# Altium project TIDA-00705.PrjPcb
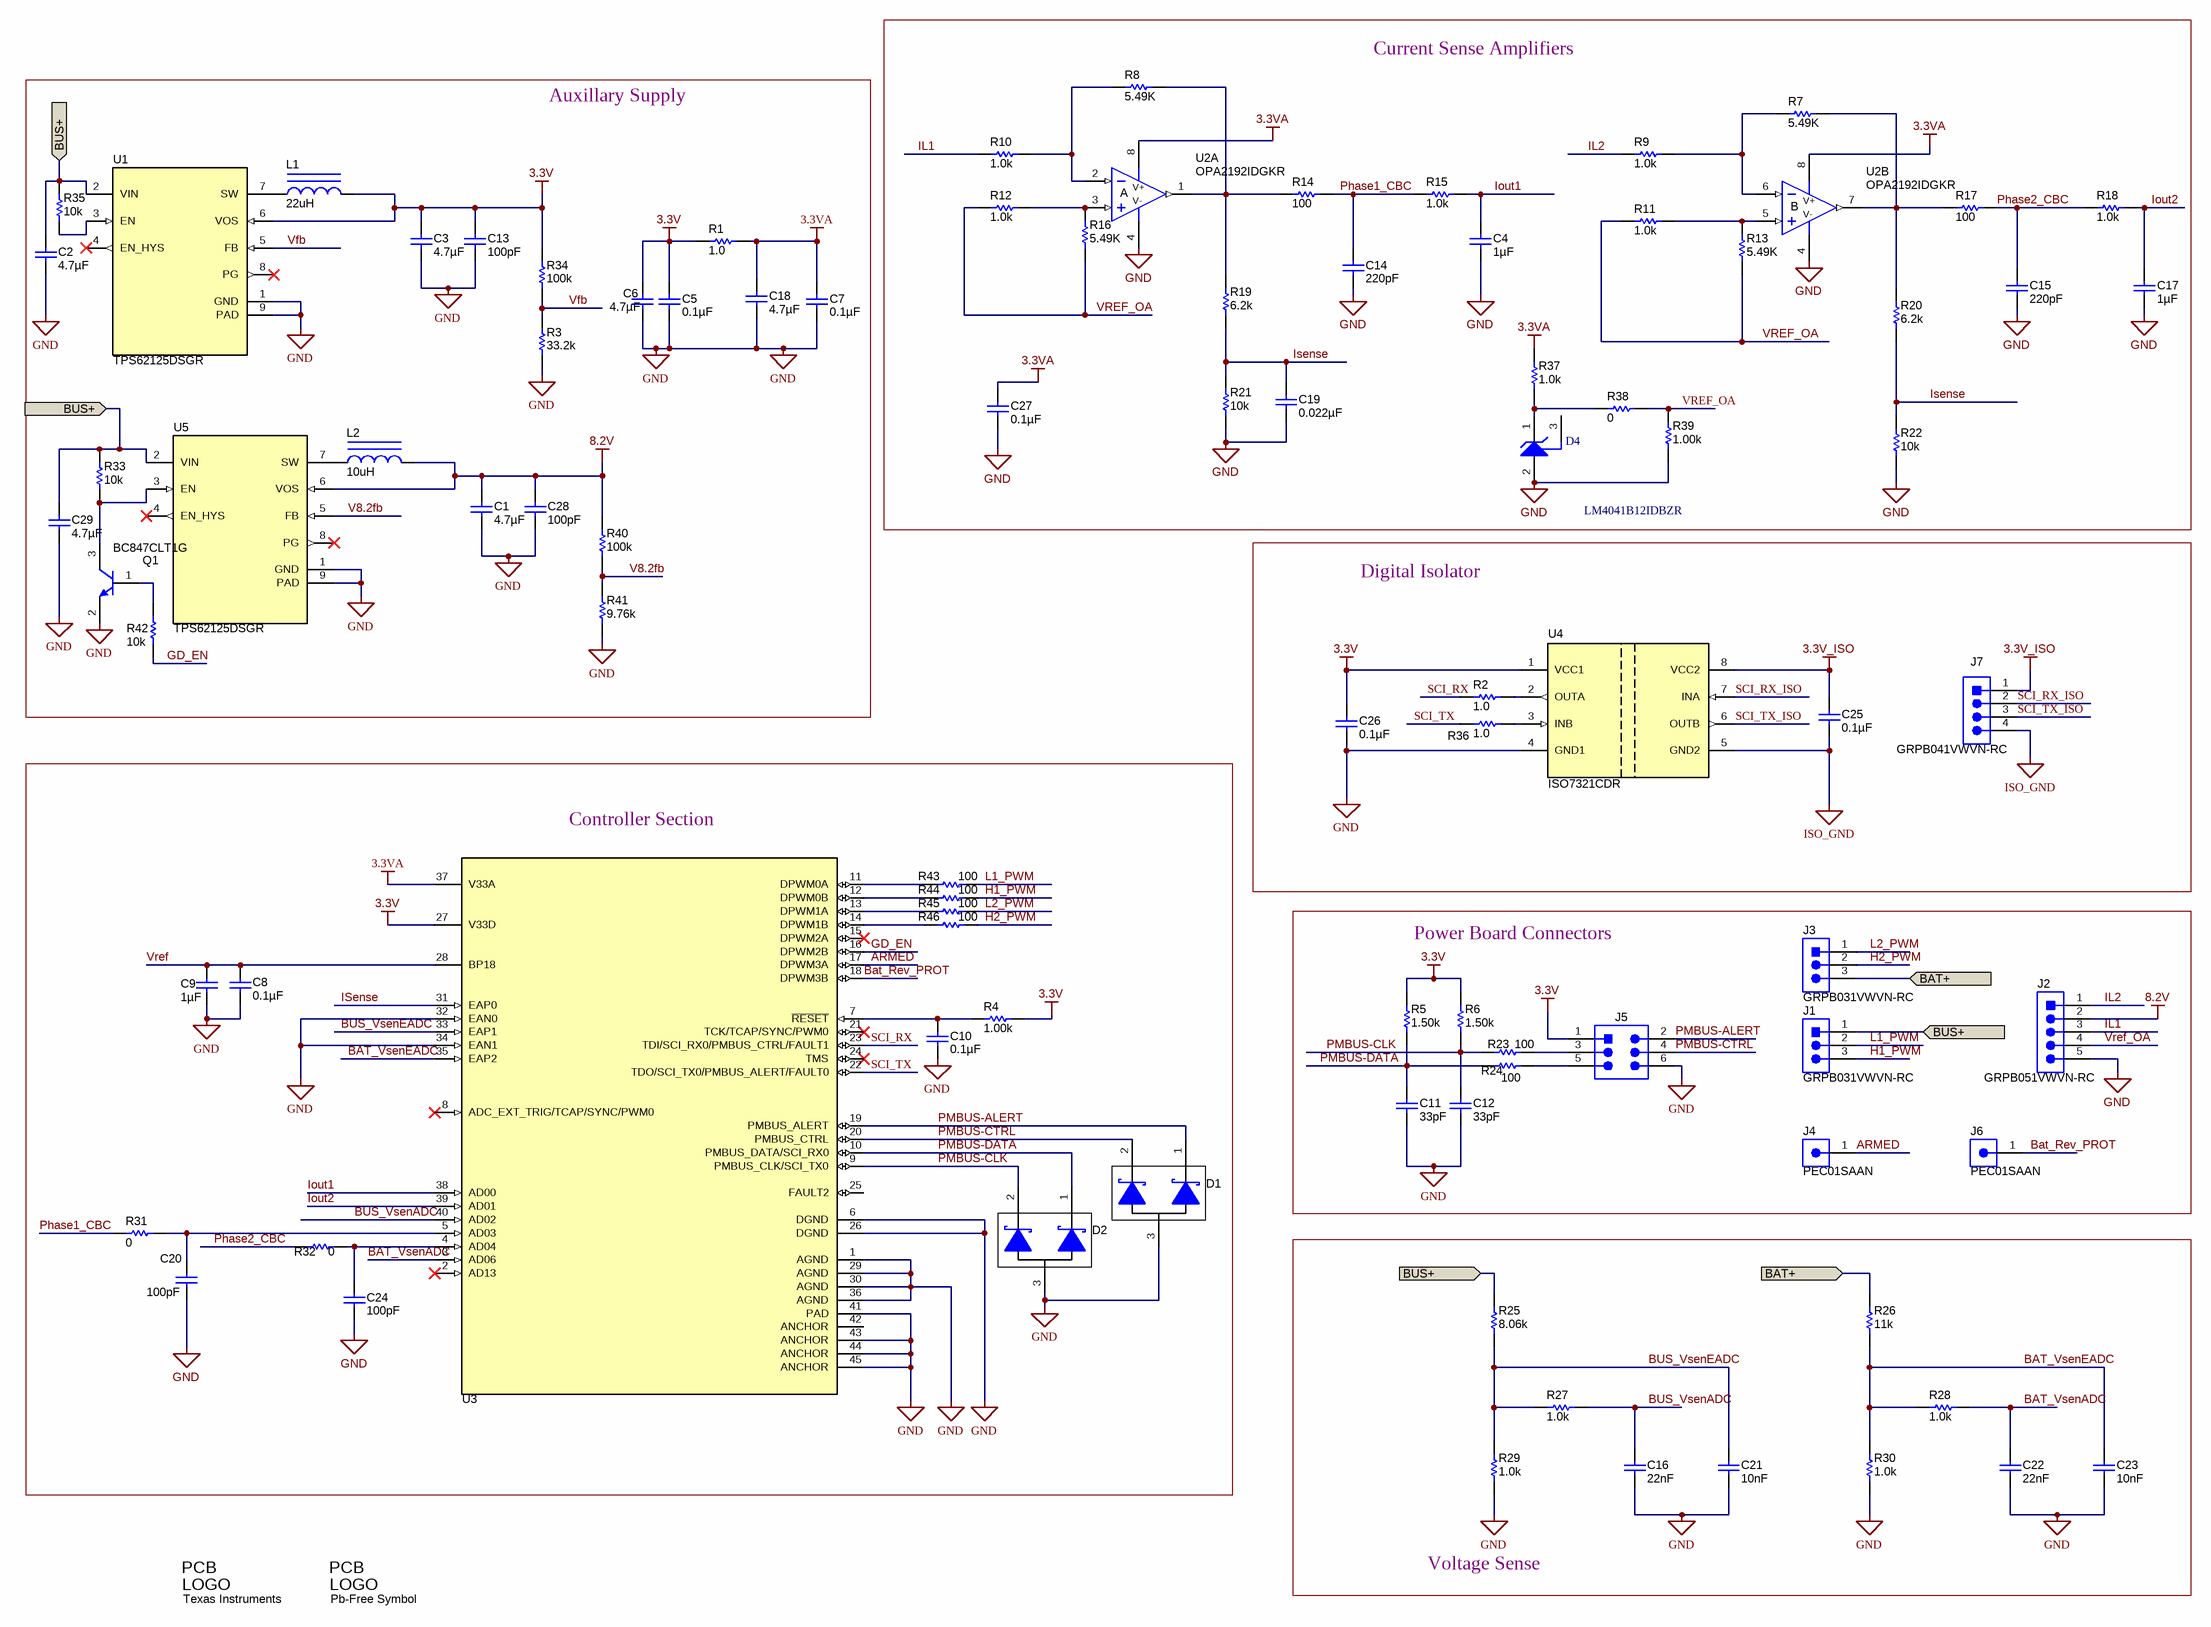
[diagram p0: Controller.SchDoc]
CopyrightYear: 2016; EVM_Orderable: N/A; PCB_Layout: Rajasekar; PCB_Rev: RevA; PRJ_Customer: Public Release; PRJ_Engineer: RAM; PRJ_Number: TIDA-00705; PRJ_Title: 720W Bidirectional Power Supply for LES; SCH_Rev: RevA; TechSupport: http://www.ti.com/support; TID: TIDA-00705
1 sheet, 95 parts. Net scope: flat (ports and power ports of the same name join across sheets).
Board file: TIDA-00705_Controller_20160414.PcbDoc

## Sheet Controller.SchDoc
size 431 x 355 mm; Date: Not shown in title block; ApprovedBy: Not shown in title block; CheckedBy: Not shown in title block; Author: Not shown in title block; CompanyName: Not shown in title block; Engineer: Not shown in title block; Organization: Not shown in title block; Address1: Not shown in title block; Address2: Not shown in title block; Address3: Not shown in title block; Address4: Not shown in title block; DocumentNumber: 1; Revision: Rev-A; SheetNumber: 1; SheetTotal: 1; PageSetup: Record=PageOptions¦CenterHorizontal=True¦CenterVertical=True¦PrintScale=1.00¦XCorrection=1.00¦YCorrection=1.00¦PrintKind=0¦BorderSize=5000000¦LeftOffset=0¦BottomOffset=0¦Orientation=2¦PaperLength=1000¦PaperWidth=1000¦Scale=100¦PaperSource=15¦PrintQuality=600¦MediaType=1¦DitherType=10¦PaperKind=Letter¦PrintScaleMode=1

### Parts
C1  ValueDisplayed: 4.7µF  [0603]  (hidden comment: CC0603KRX5R7BB475)
C2  ValueDisplayed: 4.7µF  [0603]  (hidden comment: CC0603KRX5R7BB475)
C3  ValueDisplayed: 4.7µF  [0603]  (hidden comment: CC0603KRX5R7BB475)
C4  ValueDisplayed: 1µF  [0402]  (hidden comment: C1005JB1V105K050BC)
C5  ValueDisplayed: 0.1µF  [0603]  (hidden comment: C0603C104K4RACTU)
C6  ValueDisplayed: 4.7µF  [0603]  (hidden comment: CC0603KRX5R7BB475)
C7  ValueDisplayed: 0.1µF  [0603]  (hidden comment: C0603C104K4RACTU)
C8  ValueDisplayed: 0.1µF  [0603]  (hidden comment: C0603C104K4RACTU)
C9  ValueDisplayed: 1µF  [0603]  (hidden comment: C0603C105K4PACTU)
C10  ValueDisplayed: 0.1µF  [0603]  (hidden comment: C0603C104K4RACTU)
C11  ValueDisplayed: 33pF  [0402]  (hidden comment: 885012005043)
C12  ValueDisplayed: 33pF  [0402]  (hidden comment: 885012005043)
C13  ValueDisplayed: 100pF  [0402]  (hidden comment: GRM1535C1H101JDD5D)
C14  ValueDisplayed: 220pF  [0402]  (hidden comment: C1005X7R1H221K)
C15  ValueDisplayed: 220pF  [0402]  (hidden comment: C1005X7R1H221K)
C16  ValueDisplayed: 22nF  [0402]  (hidden comment: GRM1535C1H101JDD5D)
C17  ValueDisplayed: 1µF  [0402]  (hidden comment: C1005JB1V105K050BC)
C18  ValueDisplayed: 4.7µF  [0603]  (hidden comment: CC0603KRX5R7BB475)
C19  ValueDisplayed: 0.022µF  [0402]  (hidden comment: C1005X7R1E223K)
C20  ValueDisplayed: 100pF  [0402]  (hidden comment: GRM1535C1H101JDD5D)
C21  ValueDisplayed: 10nF  [0402]  (hidden comment: GRM1535C1H101JDD5D)
C22  ValueDisplayed: 22nF  [0402]  (hidden comment: GRM1535C1H101JDD5D)
C23  ValueDisplayed: 10nF  [0402]  (hidden comment: GRM1535C1H101JDD5D)
C24  ValueDisplayed: 100pF  [0402]  (hidden comment: GRM1535C1H101JDD5D)
C25  ValueDisplayed: 0.1µF  [0603]  (hidden comment: 08053C104KAT2A)
C26  ValueDisplayed: 0.1µF  [0603]  (hidden comment: 08053C104KAT2A)
C27  ValueDisplayed: 0.1µF  [0402]  (hidden comment: C1005X7R1H104M)
C28  ValueDisplayed: 100pF  [0402]  (hidden comment: GRM1535C1H101JDD5D)
C29  ValueDisplayed: 4.7µF  [0603]  (hidden comment: CC0603KRX5R7BB475)
D1  SDM20N40A-7-F  [SOT-23]  (value not drawn)
D2  SDM20N40A-7-F  [SOT-23]  (value not drawn)
D4  LM4041B12IDBZR  [DBZ0003A_N]
J1  GRPB031VWVN-RC  [Sullins_GRPB031VWVN-RC]
J2  GRPB051VWVN-RC  [Sullins_GRPB051VWVN-RC]
J3  GRPB031VWVN-RC  [Sullins_GRPB031VWVN-RC]
J4  PEC01SAAN  [Sullins_PEC01SAAN]
J5  GRPB032VWVN-RC  [Sullins_GRPB032VWVN-RC]  (value not drawn)
J6  PEC01SAAN  [Sullins_PEC01SAAN]
J7  GRPB041VWVN-RC  [Sullins_GRPB041VWVN-RC]
L1  22uH  [WE_LQS_252012]
L2  10uH  [WE_LQS_252012]
Logo1  Texas Instruments  [TI_Symbol_Overlay_Small]  (no BOM)
Logo2  Pb-Free Symbol  [Pb-Free_Overlay_Small]  (no BOM)
Q1  BC847CLT1G  [SOT-23]
R1  ValueDisplayed: 1.0  [0402]  (hidden comment: CRCW04021R00JNED)
R2  ValueDisplayed: 1.0  [0402]  (hidden comment: CRCW04021R00JNED)
R3  ValueDisplayed: 33.2k  [0402]  (hidden comment: CRCW040233K2FKED)
R4  ValueDisplayed: 1.00k  [0402]  (hidden comment: ERJ-2RKF1001X)
R5  ValueDisplayed: 1.50k  [0402]  (hidden comment: CRCW04021K50FKED)
R6  ValueDisplayed: 1.50k  [0402]  (hidden comment: CRCW04021K50FKED)
R7  ValueDisplayed: 5.49K  [0402]  (hidden comment: ERA-2AEB5491X)
R8  ValueDisplayed: 5.49K  [0402]  (hidden comment: ERA-2AEB5491X)
R9  ValueDisplayed: 1.0k  [0402]  (hidden comment: RT0402BRD071KL)
R10  ValueDisplayed: 1.0k  [0402]  (hidden comment: RT0402BRD071KL)
R11  ValueDisplayed: 1.0k  [0402]  (hidden comment: RT0402BRD071KL)
R12  ValueDisplayed: 1.0k  [0402]  (hidden comment: RT0402BRD071KL)
R13  ValueDisplayed: 5.49K  [0402]  (hidden comment: ERA-2AEB5491X)
R14  ValueDisplayed: 100  [0402]  (hidden comment: RC0402FR-07100RL)
R15  ValueDisplayed: 1.0k  [0402]  (hidden comment: RT0402BRD071KL)
R16  ValueDisplayed: 5.49K  [0402]  (hidden comment: ERA-2AEB5491X)
R17  ValueDisplayed: 100  [0402]  (hidden comment: RC0402FR-07100RL)
R18  ValueDisplayed: 1.0k  [0402]  (hidden comment: RT0402BRD071KL)
R19  ValueDisplayed: 6.2k  [0402]  (hidden comment: RG1005P-622-B-T5)
R20  ValueDisplayed: 6.2k  [0402]  (hidden comment: RG1005P-622-B-T5)
R21  ValueDisplayed: 10k  [0402]  (hidden comment: ERA-2AEB103X)
R22  ValueDisplayed: 10k  [0402]  (hidden comment: ERA-2AEB103X)
R23  ValueDisplayed: 100  [0402]  (hidden comment: CRCW0402100RFKED)
R24  ValueDisplayed: 100  [0402]  (hidden comment: CRCW0402100RFKED)
R25  ValueDisplayed: 8.06k  [0402]  (hidden comment: CRCW04021K65FKED)
R26  ValueDisplayed: 11k  [0402]  (hidden comment: RG1005P-113-B-T5)
R27  ValueDisplayed: 1.0k  [0402]  (hidden comment: RT0402BRD071KL)
R28  ValueDisplayed: 1.0k  [0402]  (hidden comment: RT0402BRD071KL)
R29  ValueDisplayed: 1.0k  [0402]  (hidden comment: RT0402BRD071KL)
R30  ValueDisplayed: 1.0k  [0402]  (hidden comment: RT0402BRD071KL)
R31  ValueDisplayed: 0  [0402]  (hidden comment: CRCW04021K05FKED)
R32  ValueDisplayed: 0  [0402]  (hidden comment: CRCW04021K05FKED)
R33  ValueDisplayed: 10k  [0402]  (hidden comment: CRCW040210K0JNED)
R34  ValueDisplayed: 100k  [0402]  (hidden comment: CRCW0402100KFKED)
R35  ValueDisplayed: 10k  [0402]  (hidden comment: CRCW040210K0JNED)
R36  ValueDisplayed: 1.0  [0402]  (hidden comment: CRCW04021R00JNED)
R37  ValueDisplayed: 1.0k  [0402]  (hidden comment: RT0402BRD071KL)
R38  ValueDisplayed: 0  [0402]  (hidden comment: CRCW04020000Z0ED)
R39  ValueDisplayed: 1.00k  [0402]  (hidden comment: ERJ-2RKF1001X)
R40  ValueDisplayed: 100k  [0402]  (hidden comment: CRCW0402100KFKED)
R41  ValueDisplayed: 9.76k  [0402]  (hidden comment: CRCW04029K76FKED)
R42  ValueDisplayed: 10k  [0402]  (hidden comment: CRCW040210K0JNED)
R43  ValueDisplayed: 100  [0402]  (hidden comment: CRCW0402100RFKED)
R44  ValueDisplayed: 100  [0402]  (hidden comment: CRCW0402100RFKED)
R45  ValueDisplayed: 100  [0402]  (hidden comment: CRCW0402100RFKED)
R46  ValueDisplayed: 100  [0402]  (hidden comment: CRCW0402100RFKED)
U1  TPS62125DSGR  [DSG0008A]
U2  OPA2192IDGKR  [DGK0008A_N]  (parts A,B of 2)
U3  UCD3138RMHR  [RMH0040A]  (value not drawn)
U4  ISO7321CDR  [D0008B_N]
U5  TPS62125DSGR  [DSG0008A]

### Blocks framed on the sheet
Current Sense Amplifiers: C4 C14 C15 C17 C19 C27 D4 R7-R22 R37-R39 U2
Auxillary Supply: C1-C3 C5-C7 C13 C18 C28 C29 L1 L2 Q1 R1 R3 R33-R35 R40-R42 U1 U5
Digital Isolator: C25 C26 J7 R2 R36 U4
Controller Section: C8-C10 C20 C24 D1 D2 R4 R31 R32 R43-R46 U3
Power Board Connectors: C11 C12 J1-J6 R5 R6 R23 R24
Voltage Sense: C16 C21-C23 R25-R30

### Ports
BAT+ (in), BUS+ (in)

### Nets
3.3V: C3.2 C5.2 C6.2 C13.1 C26.1 J5.1 L1.2 R1.1 R4.2 R5.2 R6.2 R34.2 U1.6(VOS) U3.27(V33D) U4.1(VCC1)
3.3V_ISO: C25.1 J7.1 U4.8(VCC2)
3.3VA: C7.2 C18.2 C27.1 R1.2 R37.2 U2.8(V+) U3.37(V33A)
8.2V: C1.2 C28.1 J2.2 L2.2 R40.2 U5.6(VOS)
GND: C1.1 C2.1 C3.1 C4.2 C5.1 C6.1 C7.1 C8.1 C9.2 C10.2 C11.2 C12.2 C13.2 C14.2 C15.2 C16.2 C17.2 C18.1 C19.2 C20.2 C21.2 C22.2 C23.2 C24.2 C26.2 C27.2 C28.2 C29.1 D1.3(A) D2.3(A) D4.2(ANODE) J2.5 J5.6 Q1.2(E) R3.1 R21.1 R22.1 R29.1 R30.1 R39.1 R41.1 U1.1(GND) U1.9(PAD) U2.4(V-) U3.1(AGND) U3.6(DGND) U3.26(DGND) U3.29(AGND) U3.30(AGND) U3.32(EAN0) U3.34(EAN1) U3.36(AGND) U3.41(PAD) U3.43(ANCHOR) U3.44(ANCHOR) U3.45(ANCHOR) U4.4(GND1) U5.1(GND) U5.9(PAD)
ISO_GND: C25.2 J7.4 U4.5(GND2)
ARMED: J4.1 U3.17(DPWM3A)
BAT+: J3.3 R26.2 ; port BAT+
Bat_Rev_PROT: J6.1 U3.18(DPWM3B)
BAT_VsenADC: C22.1 R28.2 U3.3(AD06)
BAT_VsenEADC: C23.1 R26.1 R28.1 R30.2 U3.35(EAP2)
BUS+: C2.2 C29.2 J1.1 R25.2 R33.2 R35.2 U1.2(VIN) U5.2(VIN) ; port BUS+
BUS_VsenADC: C16.1 R27.2 U3.40(AD02)
BUS_VsenEADC: C21.1 R25.1 R27.1 R29.2 U3.33(EAP1)
GD_EN: R42.1 U3.16(DPWM2B)
H1_PWM: J1.3 R44.2
H2_PWM: J3.2 R46.2
IL1: J2.3 R10.1
IL2: J2.1 R9.1
Iout1: C4.1 R15.2 U3.38(AD00)
Iout2: C17.1 R18.2 U3.39(AD01)
Isense: C19.1 R19.1 R20.1 R21.2 R22.2 U3.31(EAP0)
L1_PWM: J1.2 R43.2
L2_PWM: J3.1 R45.2
Phase1_CBC: C14.1 R14.2 R15.1 R31.2
Phase2_CBC: C15.1 R17.2 R18.1 R32.2
PMBUS-ALERT: D1.1(A) J5.2 U3.19(PMBUS_ALERT)
PMBUS-CLK: C12.1 D2.2(K) R6.1 R23.1 U3.9(PMBUS_CLK/SCI_TX0)
PMBUS-CTRL: D1.2(K) J5.4 U3.20(PMBUS_CTRL)
PMBUS-DATA: C11.1 D2.1(A) R5.1 R24.1 U3.10(PMBUS_DATA/SCI_RX0)
SCI_RX: R2.1 U3.23(TDI/SCI_RX0/PMBUS_CTRL/FAULT1)
SCI_RX_ISO: J7.2 U4.7(INA)
SCI_TX: R36.1 U3.22(TDO/SCI_TX0/PMBUS_ALERT/FAULT0)
SCI_TX_ISO: J7.3 U4.6(OUTB)
V8.2fb: R40.1 R41.2 U5.5(FB)
Vfb: R3.2 R34.1 U1.5(FB)
Vref: C8.2 C9.1 U3.28(BP18)
VREF_OA: J2.4 R11.1 R12.1 R13.1 R16.1 R38.2 R39.2
NetC10_1: C10.1 R4.1 U3.7(~{RESET})
NetC20_1: C20.1 R31.1 U3.5(AD03)
NetC24_1: C24.1 R32.1 U3.4(AD04)
NetD4_1: D4.1(CATHODE) R37.1 R38.1
NetJ5_3: J5.3 R23.2
NetJ5_5: J5.5 R24.2
NetL1_1: L1.1 U1.7(SW)
NetL2_1: L2.1 U5.7(SW)
NetQ1_1: Q1.1(B) R42.2
NetQ1_3: Q1.3(C) R33.1 U5.3(EN)
NetR2_2: R2.2 U4.2(OUTA)
NetR7_1: R7.1 R17.1 R20.2 U2.7(OUT)
NetR7_2: R7.2 R9.2 U2.6(IN-)
NetR8_1: R8.1 R10.2 U2.2(IN-)
NetR8_2: R8.2 R14.1 R19.2 U2.1(OUT)
NetR11_2: R11.2 R13.2 U2.5(IN+)
NetR12_2: R12.2 R16.2 U2.3(IN+)
NetR35_1: R35.1 U1.3(EN)
NetR36_2: R36.2 U4.3(INB)
NetR43_1: R43.1 U3.11(DPWM0A)
NetR44_1: R44.1 U3.12(DPWM0B)
NetR45_1: R45.1 U3.13(DPWM1A)
NetR46_1: R46.1 U3.14(DPWM1B)

Not connected (* = marked no-connect by the designer): D4 3(NC); U1 4(EN_HYS)* 8(PG)*; U3 2(AD13)* 8(ADC_EXT_TRIG/TCAP/SYNC/PWM0)* 15(DPWM2A)* 21(TCK/TCAP/SYNC/PWM0)* 24(TMS)* 25(FAULT2) 42(ANCHOR); U5 4(EN_HYS)* 8(PG)*

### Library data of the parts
C1-C3 C6 C18 C29 = GRM188R61C475KAAJ: CAP, CERM, 4.7 µF, 16 V, +/- 10%, X5R, 0603; Manufacturer: Yageo; Value: 4.7uF; Polarized: N; CompType: Capacitor; U/M: EA; Cap_F: 0.0000047; Tolerance_%: 10; Value1: Unknown; VDC_V: 16; Value2: 16V; TaMin_C: -55; TaMax_C: 85
C4 C17 = C1005JB1V105K050BC: CAP, CERM, 1 µF, 35 V, +/- 10%, JB, 0402; Manufacturer: TDK; Polarized: N; CompType: Capacitor; Value: 1uF; U/M: EA; Cap_F: 0.000001; Tolerance_%: 10; Value1: Unknown; VDC_V: 35; Value2: 35V; TaMin_C: -25; TaMax_C: 85
C5 C7 C8 C10 = C0603C104K4RACTU: CAP, CERM, 0.1 µF, 16 V, +/- 10%, X7R, 0603; Manufacturer: Kemet; Value: 0.1uF; Polarized: N; CompType: Capacitor; U/M: EA; Cap_F: 0.0000001; Tolerance_%: 10; Value1: Unknown; VDC_V: 16; Value2: 16V; TaMin_C: -55; TaMax_C: 125
C9 = C0603C105K4PACTU: CAP, CERM, 1 µF, 16 V, +/- 10%, X5R, 0603; Manufacturer: Kemet; Polarized: N; CompType: Capacitor; Value: 1uF; U/M: EA; Cap_F: 0.000001; Tolerance_%: 10; Value1: Unknown; VDC_V: 16; Value2: 16V; TaMin_C: -55; TaMax_C: 85
C11 C12 = 885012005043: CAP, CERM, 33 pF, 25 V, +/- 5%, C0G/NP0, 0402; Manufacturer: Wurth Elektronik; Polarized: N; CompType: Capacitor; Value: 33pF; U/M: EA; Cap_F: 0.000000000033; Tolerance_%: 5; Value1: Unknown; VDC_V: 25; Value2: 25V; TaMin_C: -55; TaMax_C: 125
C13 C20-C24 C28 = GRM1535C1H101JDD5D: CAP, CERM, 100 pF, 50 V, +/- 5%, C0G/NP0, 0402; Manufacturer: MuRata; Polarized: N; CompType: Capacitor; Value: 100pF; U/M: EA; Cap_F: 0.0000000001; Tolerance_%: 5; Value1: Unknown; VDC_V: 50; Value2: 50V; TaMin_C: -55; TaMax_C: 125
C14 C15 = C1005X7R1H221K: CAP, CERM, 220 pF, 50 V, +/- 10%, X7R, 0402; Manufacturer: TDK; Polarized: N; CompType: Capacitor; Value: 220pF; U/M: EA; Cap_F: 0.00000000022; Tolerance_%: 10; ESR_ohm: 0.59; Value1: 0.59 ohm; VDC_V: 50; Value2: 50V; TaMin_C: -55; TaMax_C: 125
C16 = GRM1535C1H101JDD5D: CAP, CERM, 100 pF, 50 V, +/- 5%, C0G/NP0, 0402; Manufacturer: MuRata; Polarized: N; CompType: Capacitor; Value: 22nF; U/M: EA; Cap_F: 0.0000000001; Tolerance_%: 5; Value1: Unknown; VDC_V: 50; Value2: 50V; TaMin_C: -55; TaMax_C: 125
C19 = C1005X7R1E223K: CAP, CERM, 0.022 µF, 25 V, +/- 10%, X7R, 0402; Manufacturer: TDK; Polarized: N; CompType: Capacitor; Value: 0.022uF; U/M: EA; Cap_F: 0.000000022; Tolerance_%: 10; ESR_ohm: 0.0419; Value1: 0.0419 ohm; VDC_V: 25; Value2: 25V; TaMin_C: -55; TaMax_C: 125
C25 C26 = 08053C104KAT2A: CAP, CERM, 0.1 µF, 25 V, +/- 10%, X7R, 0805; Manufacturer: AVX; Polarized: N; CompType: Capacitor; Value: 0.1uF; U/M: EA; Cap_F: 0.0000001; Tolerance_%: 10; ESR_ohm: 0.28; Value1: 0.28 ohm; VDC_V: 25; Value2: 25V; TaMin_C: -55; TaMax_C: 125; Cap_Case: 0805
C27 = C1005X7R1H104M: CAP, CERM, 0.1 µF, 50 V, +/- 20%, X7R, 0402; Manufacturer: TDK; Polarized: N; CompType: Capacitor; Value: 0.1uF; U/M: EA; Cap_F: 0.0000001; Tolerance_%: 20; Value1: Unknown; VDC_V: 50; Value2: 50V; TaMin_C: -55; TaMax_C: 125
D1 D2 = SDM20N40A-7-F: Diode, Schottky, 40 V, 0.2 A, SOT-23; Manufacturer: Diodes Inc.; SymbolCreator: a0412235; U/M: EA; Vf_V: 0.45; Value: 40V; Value1: 0.2A; Value2: 0.45V; Io_A: 0.2; Vr_V: 40
D4 = LM4041B12IDBZR: Precision Micropower Shunt Voltage Reference, 0.2% accuracy, 1.2 V, 15 ppm / degC, 12 mA, -40 to 85 degC, 3-pin SOT-23 (DBZ), Green (RoHS & no Sb/Br); Manufacturer: Texas Instruments; Alternate PartNumber: Equivalent; Initial Accuracy @ 25/deg C(%): 0.2; Iout/Iz(Max)(mA): 12; Min Iz for Regulation(uA): 60; Rating: Catalog; Temp Coeff(Max)(ppm/ degree C): 100; Temp Coeff(Typ)(ppm/ degree C): 15; VO(V): 1.2
J1 J3 = GRPB031VWVN-RC: Header, 50mil, 3x1, Gold, TH; Manufacturer: Sullins Connector Solutions; SymbolCreator: a0799628; Gender: Male; Shrouded: N; Row_Count: 1
J2 = GRPB051VWVN-RC: Header, 50mil, 5x1, Gold, TH; Manufacturer: Sullins Connector Solutions; SymbolCreator: a0412235
J4 J6 = PEC01SAAN: Header, 1x1, Tin, TH; Manufacturer: Sullins Connector Solutions; SymbolCreator: a0412235; Pitch_mm: 2.54; Gender: Male; Shrouded: N; Row_Count: 1; Current_A: 3; Voltage_V: 1800; Cert_UL: Y
J5 = GRPB032VWVN-RC: Header, 50mil, 3x2, Gold, TH; Manufacturer: Sullins Connector Solutions; SymbolCreator: a0412235
J7 = GRPB041VWVN-RC: Header, 50mil, 4x1, Gold, TH; Manufacturer: Sullins Connector Solutions; SymbolCreator: a0412235
L1 = 74404024220: Inductor, Wirewound, Ferrite, 22 µH, 0.45 A, 0.91 ohm, SMD; Manufacturer: Wurth Elektronik; Ind_H: 22.0E-6; ValueDisplayed: 22µH; Imax_A: 0.45; Irms: 0.45A @ 40C rise; Isat: 0.55A @ 30% inductance drop; DCR_ohm: 0.91; Value2: 0.45A
L2 = 74404024100: Inductor, Wirewound, Ferrite, 10 µH, 0.47 A, 0.435 ohm, SMD; Manufacturer: Wurth Elektronik; Ind_H: 10.0E-6; ValueDisplayed: 10µH; Imax_A: 0.47; Irms: 0.47A @ 40C rise; Isat: 0.85A @ 30% inductance drop; DCR_ohm: 0.435; Value2: 0.47A
Logo1 = TI_Logo: Texas Instrument Corporate Signature; SymbolCreator: codlsc
Logo2 = Pb-Free: SymbolCreator: a0412235
Q1 = BC847CLT1G, ON Semiconductor: Transistor, NPN, 45 V, 0.1 A, SOT-23; CompType: BJT; PNP: 0; NPN: 1; Vceo_V: 45; Vcesat1_V: 0.7; Value: 45 V; IcRated_A: 0.1; Value1: 0.1 A; HfeMax: 800; TaMin_C: -55; TaMax_C: 150; U/M: EA
R1 R2 R36 = CRCW04021R00JNED: RES, 1.0, 5%, 0.063 W, 0402; Manufacturer: Vishay-Dale; CompType: Resistor; Value: 1.0; Res_ohm: 1; Value_Code: 1R00; Tolerance_%: 5; Power_W: 0.063; Value2: 0.063W; VDC_V: 50; TempCo: 200 ppm/C; EIA_Code: E24; U/M: EA
R3 = CRCW040233K2FKED: RES, 33.2 k, 1%, 0.063 W, 0402; Manufacturer: Vishay-Dale; CompType: Resistor; Value: 33.2k; Res_ohm: 33200; Value_Code: 33k2; Tolerance_%: 1; Power_W: 0.063; Value2: 0.063W; VDC_V: 50; TempCo: 100 ppm/C; EIA_Code: E96; U/M: EA
R4 R39 = ERJ-2RKF1001X: RES, 1.00 k, 1%, 0.1 W, 0402; Manufacturer: Panasonic; CompType: Resistor; Value: 1.00k; Res_ohm: 1000; Value_Code: 1k00; Tolerance_%: 1; Power_W: 0.1; Value2: 0.1W; VDC_V: 50; TempCo: 100 ppm/C; EIA_Code: E96; U/M: EA
R5 R6 = CRCW04021K50FKED: RES, 1.50 k, 1%, 0.063 W, 0402; Manufacturer: Vishay-Dale; CompType: Resistor; Value: 1.50k; Res_ohm: 1500; Value_Code: 1k50; Tolerance_%: 1; Power_W: 0.063; Value2: 0.063W; VDC_V: 50; TempCo: 100 ppm/C; EIA_Code: E96; U/M: EA
R7 R8 R13 R16 = CRCW04021K05FKED: RES, 5.49 k, 0.1%, 0.063 W, 0402; Manufacturer: Panasonic Electronic Corporation; CompType: Resistor; Value: 5.49K; Res_ohm: 5490; Tolerance_%: 1; Power_W: 0.063; Value2: 0.063W; VDC_V: 50; TempCo: 100 ppm/C; EIA_Code: E96; U/M: EA
R9-R11 R15 R27-R30 R37 = CRCW04021K05FKED: RES, 1.0 k, 0.1%, 0.063 W, 0402; Manufacturer: Vishay-Dale; CompType: Resistor; Value: 1.0k; Res_ohm: 1050; Value_Code: 1k; Tolerance_%: 1; Power_W: 0.063; Value2: 0.063W; VDC_V: 50; TempCo: 100 ppm/C; EIA_Code: E96; U/M: EA
R12 R18 = CRCW04021K05FKED: RES, 1.0 k, 0.1%, 0.063 W, 0402; Manufacturer: Vishay-Dale; CompType: Resistor; Value: 1.0k; Res_ohm: 1000; Value_Code: 1k; Tolerance_%: 1; Power_W: 0.063; Value2: 0.063W; VDC_V: 50; TempCo: 100 ppm/C; EIA_Code: E96; U/M: EA
R14 = CRCW04021K05FKED: RES, 100 1%, 0.063 W, 0402; Manufacturer: Vishay-Dale; CompType: Resistor; Value: 100; Res_ohm: 1050; Tolerance_%: 1; Power_W: 0.063; Value2: 0.063W; VDC_V: 50; TempCo: 100 ppm/C; EIA_Code: E96; U/M: EA
R17 = CRCW04021K05FKED: RES, 100, 1%, 0.063 W, 0402; Manufacturer: Vishay-Dale; CompType: Resistor; Value: 100; Tolerance_%: 1; Power_W: 0.063; Value2: 0.063W; VDC_V: 50; TempCo: 100 ppm/C; EIA_Code: E96; U/M: EA
R19 R20 = CRCW04021K05FKED: RES, 6.2 k, 0.1%, 0.063 W, 0402; Manufacturer: Susumu; CompType: Resistor; Value: 6.2k; Res_ohm: 6200; Tolerance_%: 1; Power_W: 0.063; Value2: 0.063W; VDC_V: 50; TempCo: 100 ppm/C; EIA_Code: E96; U/M: EA
R21 R22 = CRCW04021K05FKED: RES, 10 k, 1%, 0.063 W, 0402; Manufacturer: Panosonic Electronic Components; CompType: Resistor; Value: 10K; Res_ohm: 10000; Tolerance_%: 1; Power_W: 0.063; Value2: 0.063W; VDC_V: 50; TempCo: 100 ppm/C; EIA_Code: E96; U/M: EA
R23 R24 = CRCW0402100RFKED: RES, 100, 1%, 0.063 W, 0402; Manufacturer: Vishay-Dale; CompType: Resistor; Value: 100; Value_Code: 100R; Tolerance_%: 1; Power_W: 0.063; Value2: 0.063W; VDC_V: 50; TempCo: 100 ppm/C; EIA_Code: E96; U/M: EA
R25 = CRCW04021K65FKED: RES, 8.06 k, 0.1%, 0.063 W, 0402; Manufacturer: Vishay-Dale; CompType: Resistor; Value: 8.06k; Res_ohm: 8060; Tolerance_%: 1; Power_W: 0.063; Value2: 0.063W; VDC_V: 50; TempCo: 100 ppm/C; EIA_Code: E96; U/M: EA
R26 = CRCW04021K65FKED: RES, 11 k, 1%, 0.063 W, 0402; Manufacturer: susumu; CompType: Resistor; Value: 11k; Res_ohm: 1650; Tolerance_%: 1; Value1: 0.1%; Power_W: 0.063; Value2: 0.063W; VDC_V: 50; TempCo: 100 ppm/C; EIA_Code: E96; U/M: EA
R31 R32 = CRCW04021K05FKED: RES, 1.05 k, 1%, 0.063 W, 0402; Manufacturer: Vishay-Dale; CompType: Resistor; Value: 0; Res_ohm: 1050; Value_Code: 1k05; Tolerance_%: 1; Power_W: 0.063; Value2: 0.063W; VDC_V: 50; TempCo: 100 ppm/C; EIA_Code: E96; U/M: EA
R33 R35 R42 = CRCW040210K0JNED: RES, 10 k, 5%, 0.063 W, 0402; Manufacturer: Vishay-Dale; CompType: Resistor; Value: 10k; Res_ohm: 10000; Value_Code: 10k0; Tolerance_%: 5; Power_W: 0.063; Value2: 0.063W; VDC_V: 50; TempCo: 200 ppm/C; EIA_Code: E24; U/M: EA
R34 R40 = CRCW0402100KFKED: RES, 100 k, 1%, 0.063 W, 0402; Manufacturer: Vishay-Dale; CompType: Resistor; Value: 100k; Res_ohm: 100000; Tolerance_%: 1; Power_W: 0.063; Value2: 0.063W; VDC_V: 50; TempCo: 100 ppm/C; EIA_Code: E96; U/M: EA
R38 = CRCW04020000Z0ED: RES, 0, 5%, 0.063 W, 0402; Manufacturer: Vishay-Dale; CompType: Resistor; Value: 0; Value_Code: 0000; Tolerance_%: 5; Power_W: 0.063; Value2: 0.063W; VDC_V: 50; TempCo: 200 ppm/C; EIA_Code: E24; U/M: EA
R41 = CRCW04029K76FKED: RES, 9.76 k, 1%, 0.063 W, 0402; Manufacturer: Vishay-Dale; CompType: Resistor; Value: 9.76k; Res_ohm: 9760; Value_Code: 9k76; Tolerance_%: 1; Power_W: 0.063; Value2: 0.063W; VDC_V: 50; TempCo: 100 ppm/C; EIA_Code: E96; U/M: EA
R43-R46 = CRCW0402100RFKED: RES, 100, 1%, 0.063 W, 0402; Manufacturer: Vishay-Dale; CompType: Resistor; Value: 100; Value_Code: 100R; Tolerance_%: 1; Power_W: 0.063; Value2: 0.063W; VDC_V: 50; TempCo: 100 ppm/C; EIA_Code: E96; U/M: EA; AEC Category: Q200
U1 U5 = TPS62125DSGR: 3V-17V, 300mA Step Down Converter With Adjustable Enable Threshold And Hysteresis, DSG0008A; Alternate PartNumber: TPS62125DSGT; Manufacturer: Texas Instruments; SymbolCreator: a0412235; CompType: IC; U/M: EA
U2 = OPA2192IDGKR: 36-V, Precision, Rail-to-Rail Input/Output, Low Offset Voltage, Low Input Bias Current Op Amp with e-trim, DGK0008A; Manufacturer: Texas Instruments; CompType: IC; U/M: EA
U3 = UCD3138RMHR: Highly Integrated Digital Controller for Isolated Power, RMH0040A; Alternate PartNumber: UCD3138RMHT; Manufacturer: Texas Instruments; SymbolCreator: Altium; CompType: IC; U/M: EA
U4 = ISO7321CDR: Robust EMC, Low Power, Dual-Channel Digital Isolators, D0008B; Manufacturer: Texas Instruments; SymbolCreator: a0411947; CompType: IC; U/M: EA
